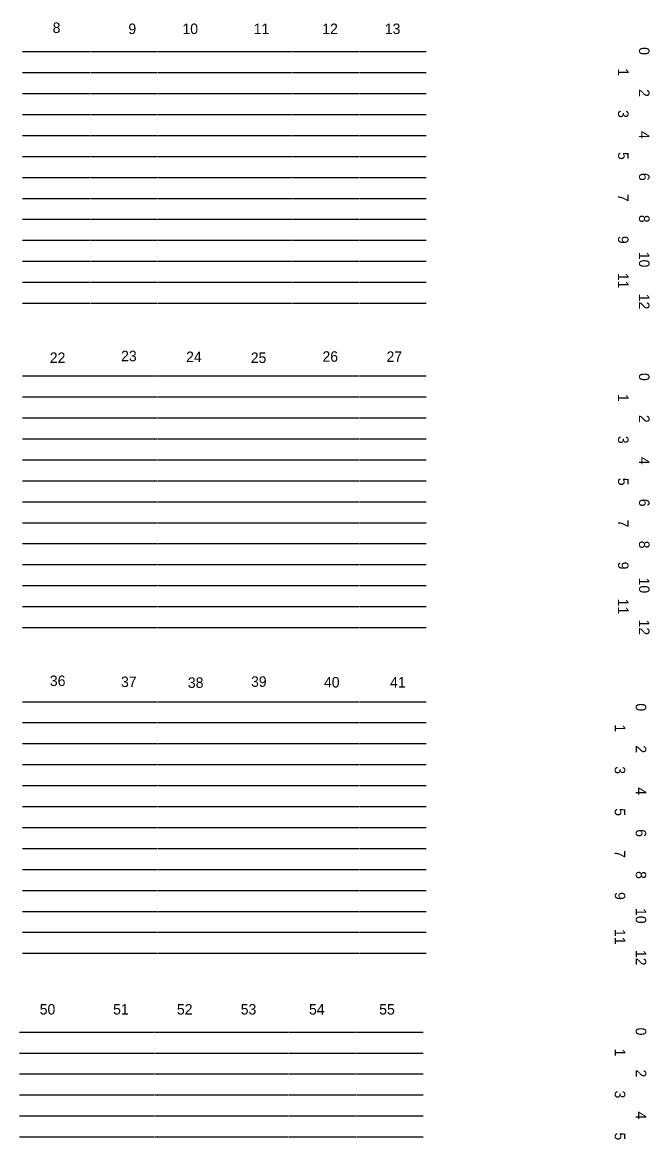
# Model space of a CAD drawing. Extents: x 11193 to 12507, y 10092 to 10555.
# Drawn here: x 11315.8 to 11445.3, y 10324.2 to 10555.1 of the extents above; entities that cross this region are included whole.
import ezdxf

# ---------------------------------------------------------------- set-up
doc = ezdxf.new("R2010")
doc.units = 0
doc.layers.add('Level 2', color=7, linetype='Continuous')

msp = doc.modelspace()

# ---------------------------------------------------------------- linework, layer by layer
at = {"layer": 'Level 2'}
for p, q in [((11315.81, 10549.04), (11329.78, 10549.04)), ((11329.88, 10549.04), (11343.66, 10549.04)), ((11343.77, 10549.04), (11357.33, 10549.04)), ((11357.44, 10549.04), (11371.41, 10549.04)), ((11371.52, 10549.04), (11385.3, 10549.04)), ((11385.41, 10549.04), (11399.15, 10549.04)), ((11315.81, 10544.71), (11329.78, 10544.71)), ((11329.88, 10544.71), (11343.66, 10544.71)), ((11343.77, 10544.71), (11357.33, 10544.71)), ((11357.44, 10544.71), (11371.41, 10544.71)), ((11371.52, 10544.71), (11385.3, 10544.71)), ((11385.41, 10544.71), (11399.15, 10544.71)), ((11315.81, 10540.38), (11329.78, 10540.38)), ((11329.88, 10540.38), (11343.66, 10540.38)), ((11343.77, 10540.38), (11357.33, 10540.38)), ((11357.44, 10540.38), (11371.41, 10540.38)), ((11371.52, 10540.38), (11385.3, 10540.38)), ((11385.41, 10540.38), (11399.15, 10540.38)), ((11315.81, 10536.05), (11329.78, 10536.05)), ((11329.88, 10536.05), (11343.66, 10536.05)), ((11343.77, 10536.05), (11357.33, 10536.05)), ((11357.44, 10536.05), (11371.41, 10536.05)), ((11371.52, 10536.05), (11385.3, 10536.05)), ((11385.41, 10536.05), (11399.15, 10536.05)), ((11315.81, 10531.72), (11329.78, 10531.72)), ((11329.88, 10531.72), (11343.66, 10531.72)), ((11343.77, 10531.72), (11357.33, 10531.72)), ((11357.44, 10531.72), (11371.41, 10531.72)), ((11371.52, 10531.72), (11385.3, 10531.72)), ((11385.41, 10531.72), (11399.15, 10531.72)), ((11315.81, 10527.38), (11329.78, 10527.38)), ((11329.88, 10527.38), (11343.66, 10527.38)), ((11343.77, 10527.38), (11357.33, 10527.38)), ((11357.44, 10527.38), (11371.41, 10527.38)), ((11371.52, 10527.38), (11385.3, 10527.38)), ((11385.41, 10527.38), (11399.15, 10527.38)), ((11315.81, 10523.05), (11329.78, 10523.05)), ((11329.88, 10523.05), (11343.66, 10523.05)), ((11343.77, 10523.05), (11357.33, 10523.05)), ((11357.44, 10523.05), (11371.41, 10523.05)), ((11371.52, 10523.05), (11385.3, 10523.05)), ((11385.41, 10523.05), (11399.15, 10523.05)), ((11315.81, 10518.72), (11329.78, 10518.72)), ((11329.88, 10518.72), (11343.66, 10518.72)), ((11343.77, 10518.72), (11357.33, 10518.72)), ((11357.44, 10518.72), (11371.41, 10518.72)), ((11371.52, 10518.72), (11385.3, 10518.72)), ((11385.41, 10518.72), (11399.15, 10518.72)), ((11315.81, 10514.39), (11329.78, 10514.39)), ((11329.88, 10514.39), (11343.66, 10514.39)), ((11343.77, 10514.39), (11357.33, 10514.39)), ((11357.44, 10514.39), (11371.41, 10514.39)), ((11371.52, 10514.39), (11385.3, 10514.39)), ((11385.41, 10514.39), (11399.15, 10514.39)), ((11315.81, 10510.06), (11329.78, 10510.06)), ((11329.88, 10510.06), (11343.66, 10510.06)), ((11343.77, 10510.06), (11357.33, 10510.06)), ((11357.44, 10510.06), (11371.41, 10510.06)), ((11371.52, 10510.06), (11385.3, 10510.06)), ((11385.41, 10510.06), (11399.15, 10510.06)), ((11315.81, 10505.72), (11329.78, 10505.72)), ((11329.88, 10505.72), (11343.66, 10505.72)), ((11343.77, 10505.72), (11357.33, 10505.72)), ((11357.44, 10505.72), (11371.41, 10505.72)), ((11371.52, 10505.72), (11385.3, 10505.72)), ((11385.41, 10505.72), (11399.15, 10505.72)), ((11315.81, 10501.39), (11329.78, 10501.39)), ((11329.88, 10501.39), (11343.66, 10501.39)), ((11343.77, 10501.39), (11357.33, 10501.39)), ((11357.44, 10501.39), (11371.41, 10501.39)), ((11371.52, 10501.39), (11385.3, 10501.39)), ((11385.41, 10501.39), (11399.15, 10501.39)), ((11315.81, 10497.06), (11329.78, 10497.06)), ((11329.88, 10497.06), (11343.66, 10497.06)), ((11343.77, 10497.06), (11357.33, 10497.06)), ((11357.44, 10497.06), (11371.41, 10497.06)), ((11371.52, 10497.06), (11385.3, 10497.06)), ((11385.41, 10497.06), (11399.15, 10497.06)), ((11315.81, 10482.04), (11329.8, 10482.04)), ((11329.9, 10482.04), (11343.67, 10482.04)), ((11343.77, 10482.04), (11357.35, 10482.04)), ((11357.45, 10482.04), (11371.43, 10482.04)), ((11371.53, 10482.04), (11385.31, 10482.04)), ((11385.42, 10482.04), (11399.15, 10482.04)), ((11315.81, 10477.71), (11329.8, 10477.71)), ((11329.9, 10477.71), (11343.67, 10477.71)), ((11343.77, 10477.71), (11357.35, 10477.71)), ((11357.45, 10477.71), (11371.43, 10477.71)), ((11371.53, 10477.71), (11385.31, 10477.71)), ((11385.42, 10477.71), (11399.15, 10477.71)), ((11315.81, 10473.37), (11329.8, 10473.37)), ((11329.9, 10473.37), (11343.67, 10473.37)), ((11343.77, 10473.37), (11357.35, 10473.37)), ((11357.45, 10473.37), (11371.43, 10473.37)), ((11371.53, 10473.37), (11385.31, 10473.37)), ((11385.42, 10473.37), (11399.15, 10473.37)), ((11315.81, 10469.04), (11329.8, 10469.04)), ((11329.9, 10469.04), (11343.67, 10469.04)), ((11343.77, 10469.04), (11357.35, 10469.04)), ((11357.45, 10469.04), (11371.43, 10469.04)), ((11371.53, 10469.04), (11385.31, 10469.04)), ((11385.42, 10469.04), (11399.15, 10469.04)), ((11315.81, 10464.71), (11329.8, 10464.71)), ((11329.9, 10464.71), (11343.67, 10464.71)), ((11343.77, 10464.71), (11357.35, 10464.71)), ((11357.45, 10464.71), (11371.43, 10464.71)), ((11371.53, 10464.71), (11385.31, 10464.71)), ((11385.42, 10464.71), (11399.15, 10464.71)), ((11315.81, 10460.38), (11329.8, 10460.38)), ((11329.9, 10460.38), (11343.67, 10460.38)), ((11343.77, 10460.38), (11357.35, 10460.38)), ((11357.45, 10460.38), (11371.43, 10460.38)), ((11371.53, 10460.38), (11385.31, 10460.38)), ((11385.42, 10460.38), (11399.15, 10460.38)), ((11315.81, 10456.05), (11329.8, 10456.05)), ((11329.9, 10456.05), (11343.67, 10456.05)), ((11343.77, 10456.05), (11357.35, 10456.05)), ((11357.45, 10456.05), (11371.43, 10456.05)), ((11371.53, 10456.05), (11385.31, 10456.05)), ((11385.42, 10456.05), (11399.15, 10456.05)), ((11315.81, 10451.71), (11329.8, 10451.71)), ((11329.9, 10451.71), (11343.67, 10451.71)), ((11343.77, 10451.71), (11357.35, 10451.71)), ((11357.45, 10451.71), (11371.43, 10451.71)), ((11371.53, 10451.71), (11385.31, 10451.71)), ((11385.42, 10451.71), (11399.15, 10451.71)), ((11315.81, 10447.38), (11329.8, 10447.38)), ((11329.9, 10447.38), (11343.67, 10447.38)), ((11343.77, 10447.38), (11357.35, 10447.38)), ((11357.45, 10447.38), (11371.43, 10447.38)), ((11371.53, 10447.38), (11385.31, 10447.38)), ((11385.42, 10447.38), (11399.15, 10447.38)), ((11315.81, 10443.05), (11329.8, 10443.05)), ((11329.9, 10443.05), (11343.67, 10443.05)), ((11343.77, 10443.05), (11357.35, 10443.05)), ((11357.45, 10443.05), (11371.43, 10443.05)), ((11371.53, 10443.05), (11385.31, 10443.05)), ((11385.42, 10443.05), (11399.15, 10443.05)), ((11315.81, 10438.72), (11329.8, 10438.72)), ((11329.9, 10438.72), (11343.67, 10438.72)), ((11343.77, 10438.72), (11357.35, 10438.72)), ((11357.45, 10438.72), (11371.43, 10438.72)), ((11371.53, 10438.72), (11385.31, 10438.72)), ((11385.42, 10438.72), (11399.15, 10438.72)), ((11315.81, 10434.39), (11329.8, 10434.39)), ((11329.9, 10434.39), (11343.67, 10434.39)), ((11343.77, 10434.39), (11357.35, 10434.39)), ((11357.45, 10434.39), (11371.43, 10434.39)), ((11371.53, 10434.39), (11385.31, 10434.39)), ((11385.42, 10434.39), (11399.15, 10434.39)), ((11315.81, 10430.05), (11329.8, 10430.05)), ((11329.9, 10430.05), (11343.67, 10430.05)), ((11343.77, 10430.05), (11357.35, 10430.05)), ((11357.45, 10430.05), (11371.43, 10430.05)), ((11371.53, 10430.05), (11385.31, 10430.05)), ((11385.42, 10430.05), (11399.15, 10430.05)), ((11315.81, 10414.72), (11329.8, 10414.72)), ((11329.9, 10414.72), (11343.67, 10414.72)), ((11343.77, 10414.72), (11357.35, 10414.72)), ((11357.45, 10414.72), (11371.43, 10414.72)), ((11371.53, 10414.72), (11385.31, 10414.72)), ((11385.42, 10414.72), (11399.15, 10414.72)), ((11315.81, 10410.39), (11329.8, 10410.39)), ((11329.9, 10410.39), (11343.67, 10410.39)), ((11343.77, 10410.39), (11357.35, 10410.39)), ((11357.45, 10410.39), (11371.43, 10410.39)), ((11371.53, 10410.39), (11385.31, 10410.39)), ((11385.42, 10410.39), (11399.15, 10410.39)), ((11315.81, 10406.06), (11329.8, 10406.06)), ((11329.9, 10406.06), (11343.67, 10406.06)), ((11343.77, 10406.06), (11357.35, 10406.06)), ((11357.45, 10406.06), (11371.43, 10406.06)), ((11371.53, 10406.06), (11385.31, 10406.06)), ((11385.42, 10406.06), (11399.15, 10406.06)), ((11315.81, 10401.72), (11329.8, 10401.72)), ((11329.9, 10401.72), (11343.67, 10401.72)), ((11343.77, 10401.72), (11357.35, 10401.72)), ((11357.45, 10401.72), (11371.43, 10401.72)), ((11371.53, 10401.72), (11385.31, 10401.72)), ((11385.42, 10401.72), (11399.15, 10401.72)), ((11315.81, 10397.39), (11329.8, 10397.39)), ((11329.9, 10397.39), (11343.67, 10397.39)), ((11343.77, 10397.39), (11357.35, 10397.39)), ((11357.45, 10397.39), (11371.43, 10397.39)), ((11371.53, 10397.39), (11385.31, 10397.39)), ((11385.42, 10397.39), (11399.15, 10397.39)), ((11315.81, 10393.06), (11329.8, 10393.06)), ((11329.9, 10393.06), (11343.67, 10393.06)), ((11343.77, 10393.06), (11357.35, 10393.06)), ((11357.45, 10393.06), (11371.43, 10393.06)), ((11371.53, 10393.06), (11385.31, 10393.06)), ((11385.42, 10393.06), (11399.15, 10393.06)), ((11315.81, 10388.73), (11329.8, 10388.73)), ((11329.9, 10388.73), (11343.67, 10388.73)), ((11343.77, 10388.73), (11357.35, 10388.73)), ((11357.45, 10388.73), (11371.43, 10388.73)), ((11371.53, 10388.73), (11385.31, 10388.73)), ((11385.42, 10388.73), (11399.15, 10388.73)), ((11315.81, 10384.4), (11329.8, 10384.4)), ((11329.9, 10384.4), (11343.67, 10384.4)), ((11343.77, 10384.4), (11357.35, 10384.4)), ((11357.45, 10384.4), (11371.43, 10384.4)), ((11371.53, 10384.4), (11385.31, 10384.4)), ((11385.42, 10384.4), (11399.15, 10384.4)), ((11315.81, 10380.06), (11329.8, 10380.06)), ((11329.9, 10380.06), (11343.67, 10380.06)), ((11343.77, 10380.06), (11357.35, 10380.06)), ((11357.45, 10380.06), (11371.43, 10380.06)), ((11371.53, 10380.06), (11385.31, 10380.06)), ((11385.42, 10380.06), (11399.15, 10380.06)), ((11315.81, 10375.73), (11329.8, 10375.73)), ((11329.9, 10375.73), (11343.67, 10375.73)), ((11343.77, 10375.73), (11357.35, 10375.73)), ((11357.45, 10375.73), (11371.43, 10375.73)), ((11371.53, 10375.73), (11385.31, 10375.73)), ((11385.42, 10375.73), (11399.15, 10375.73)), ((11315.81, 10371.4), (11329.8, 10371.4)), ((11329.9, 10371.4), (11343.67, 10371.4)), ((11343.77, 10371.4), (11357.35, 10371.4)), ((11357.45, 10371.4), (11371.43, 10371.4)), ((11371.53, 10371.4), (11385.31, 10371.4)), ((11385.42, 10371.4), (11399.15, 10371.4)), ((11315.81, 10367.07), (11329.8, 10367.07)), ((11329.9, 10367.07), (11343.67, 10367.07)), ((11343.77, 10367.07), (11357.35, 10367.07)), ((11357.45, 10367.07), (11371.43, 10367.07)), ((11371.53, 10367.07), (11385.31, 10367.07)), ((11385.42, 10367.07), (11399.15, 10367.07)), ((11315.81, 10362.74), (11329.8, 10362.74)), ((11329.9, 10362.74), (11343.67, 10362.74)), ((11343.77, 10362.74), (11357.35, 10362.74)), ((11357.45, 10362.74), (11371.43, 10362.74)), ((11371.53, 10362.74), (11385.31, 10362.74)), ((11385.42, 10362.74), (11399.15, 10362.74)), ((11315.14, 10346.46), (11329.11, 10346.46)), ((11329.21, 10346.46), (11342.99, 10346.46)), ((11343.1, 10346.46), (11356.66, 10346.46)), ((11356.77, 10346.46), (11370.74, 10346.46)), ((11370.85, 10346.46), (11384.63, 10346.46)), ((11384.74, 10346.46), (11398.48, 10346.46)), ((11315.14, 10342.13), (11329.11, 10342.13)), ((11329.21, 10342.13), (11342.99, 10342.13)), ((11343.1, 10342.13), (11356.66, 10342.13)), ((11356.77, 10342.13), (11370.74, 10342.13)), ((11370.85, 10342.13), (11384.63, 10342.13)), ((11384.74, 10342.13), (11398.48, 10342.13)), ((11315.14, 10337.8), (11329.11, 10337.8)), ((11329.21, 10337.8), (11342.99, 10337.8)), ((11343.1, 10337.8), (11356.66, 10337.8)), ((11356.77, 10337.8), (11370.74, 10337.8)), ((11370.85, 10337.8), (11384.63, 10337.8)), ((11384.74, 10337.8), (11398.48, 10337.8)), ((11315.14, 10333.47), (11329.11, 10333.47)), ((11329.21, 10333.47), (11342.99, 10333.47)), ((11343.1, 10333.47), (11356.66, 10333.47)), ((11356.77, 10333.47), (11370.74, 10333.47)), ((11370.85, 10333.47), (11384.63, 10333.47)), ((11384.74, 10333.47), (11398.48, 10333.47)), ((11315.14, 10329.14), (11329.11, 10329.14)), ((11329.21, 10329.14), (11342.99, 10329.14)), ((11343.1, 10329.14), (11356.66, 10329.14)), ((11356.77, 10329.14), (11370.74, 10329.14)), ((11370.85, 10329.14), (11384.63, 10329.14)), ((11384.74, 10329.14), (11398.48, 10329.14)), ((11315.14, 10324.8), (11329.11, 10324.8)), ((11329.21, 10324.8), (11342.99, 10324.8)), ((11343.1, 10324.8), (11356.66, 10324.8)), ((11356.77, 10324.8), (11370.74, 10324.8)), ((11370.85, 10324.8), (11384.63, 10324.8)), ((11384.74, 10324.8), (11398.48, 10324.8))]:
    msp.add_line(p, q, dxfattribs=at)

# ---------------------------------------------------------------- texts
for s, height, p in [('8', 2.17, (11322.01, 10552.89)), ('9', 2.17, (11337.65, 10552.67)), ('10', 2.166, (11348.81, 10552.67)), ('11', 2.166, (11363.51, 10552.67)), ('12', 2.166, (11377.68, 10552.67)), ('13', 2.166, (11390.59, 10552.67)), ('22', 2.166, (11321.42, 10484.71)), ('23', 2.166, (11336.15, 10485.07)), ('24', 2.166, (11349.57, 10484.9)), ('25', 2.166, (11362.92, 10484.71)), ('26', 2.166, (11377.72, 10484.96)), ('27', 2.166, (11390.95, 10484.94)), ('36', 2.166, (11321.44, 10417.96)), ('37', 2.166, (11336.13, 10417.75)), ('38', 2.166, (11349.93, 10417.58)), ('39', 2.166, (11362.97, 10417.79)), ('40', 2.166, (11378.03, 10417.66)), ('41', 2.166, (11391.67, 10417.64)), ('50', 2.17, (11319.34, 10350.08)), ('51', 2.17, (11334.5, 10350.08)), ('52', 2.17, (11347.67, 10350.08)), ('53', 2.17, (11360.84, 10350.08)), ('54', 2.17, (11374.94, 10350.08)), ('55', 2.17, (11389.43, 10350.08))]:
    msp.add_text(s, height=height, dxfattribs=at).set_placement(p)
for s, height, p in [('0', 2.17, (11443.07, 10549.96)), ('1', 2.17, (11438.74, 10545.63)), ('2', 2.17, (11443.07, 10541.3)), ('3', 2.17, (11438.74, 10536.96)), ('4', 2.17, (11443.07, 10532.63)), ('5', 2.17, (11438.74, 10528.3)), ('6', 2.17, (11443.07, 10523.97)), ('7', 2.17, (11438.74, 10519.64)), ('8', 2.17, (11443.07, 10515.3)), ('9', 2.17, (11438.74, 10510.97)), ('10', 2.166, (11443.07, 10507.68)), ('11', 2.166, (11438.74, 10503.34)), ('12', 2.166, (11443.07, 10499.01)), ('0', 2.17, (11443.07, 10482.64)), ('1', 2.17, (11438.74, 10478.31)), ('2', 2.17, (11443.07, 10473.98)), ('3', 2.17, (11438.74, 10469.64)), ('4', 2.17, (11443.07, 10465.31)), ('5', 2.17, (11438.74, 10460.98)), ('6', 2.17, (11443.07, 10456.65)), ('7', 2.17, (11438.74, 10452.32)), ('8', 2.17, (11443.07, 10447.98)), ('9', 2.17, (11438.74, 10443.65)), ('10', 2.166, (11443.07, 10440.36)), ('11', 2.166, (11438.74, 10436.02)), ('12', 2.166, (11443.07, 10431.69)), ('0', 2.17, (11442.4, 10414.38)), ('1', 2.17, (11438.07, 10410.04)), ('2', 2.17, (11442.4, 10405.71)), ('3', 2.17, (11438.07, 10401.38)), ('4', 2.17, (11442.4, 10397.05)), ('5', 2.17, (11438.07, 10392.72)), ('6', 2.17, (11442.4, 10388.38)), ('7', 2.17, (11438.07, 10384.05)), ('8', 2.17, (11442.4, 10379.72)), ('9', 2.17, (11438.07, 10375.39)), ('10', 2.166, (11442.4, 10372.09)), ('11', 2.166, (11438.07, 10367.76)), ('12', 2.166, (11442.4, 10363.43)), ('0', 2.17, (11442.4, 10347.38)), ('1', 2.17, (11438.07, 10343.05)), ('2', 2.17, (11442.4, 10338.72)), ('3', 2.17, (11438.07, 10334.38)), ('4', 2.17, (11442.4, 10330.05)), ('5', 2.17, (11438.07, 10325.72))]:
    msp.add_text(s, height=height, rotation=270, dxfattribs=at).set_placement(p)

doc.saveas('drawing.dxf')
